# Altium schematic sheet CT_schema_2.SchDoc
size 276 x 169 mm
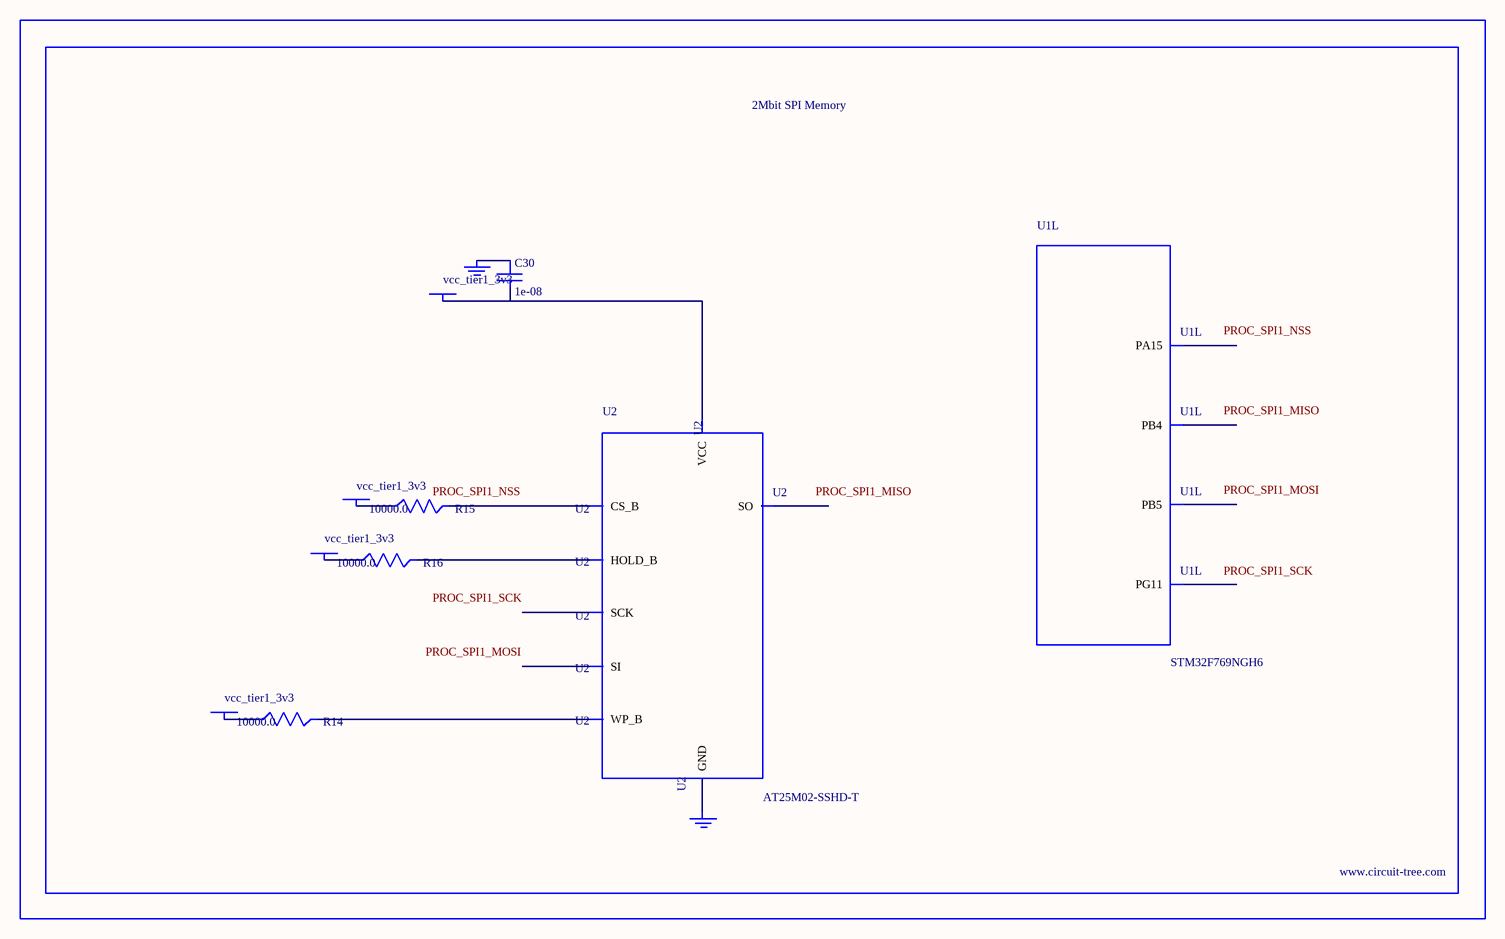
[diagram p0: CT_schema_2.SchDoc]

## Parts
BORDER1  (no value)
C30  1e-08  [C0402]
GND_INSTANCE_1_0  (no value)
GND_INSTANCE_1_1  (no value)
POWER_INSTANCE_1_0  vcc_tier1_3v3
POWER_INSTANCE_1_1  vcc_tier1_3v3
POWER_INSTANCE_1_2  vcc_tier1_3v3
POWER_INSTANCE_1_3  vcc_tier1_3v3
R14  10000.0  [R0603]
R15  10000.0  [R0603]
R16  10000.0  [R0603]
U1  STM32F769NGH6  [TFBGA216]  (part L of 17)
U2  AT25M02-SSHD-T  [SOIC-8]

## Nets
NetC30_1: C30.1 GND_INSTANCE_1_0.0(GND)
NetC30_2: C30.2 POWER_INSTANCE_1_3.0(PWR) U2.8(VCC)
NetGND_INSTANCE_1_1_0: GND_INSTANCE_1_1.0(GND) U2.4(GND)
NetPOWER_INSTANCE_1_0_0: POWER_INSTANCE_1_0.0(PWR) R15.1
NetPOWER_INSTANCE_1_1_0: POWER_INSTANCE_1_1.0(PWR) R14.1
NetPOWER_INSTANCE_1_2_0: POWER_INSTANCE_1_2.0(PWR) R16.1
NetR14_2: R14.2 U2.3(WP_B)
NetR15_2: R15.2 U2.1(CS_B)
NetR16_2: R16.2 U2.7(HOLD_B)

Not connected (* = marked no-connect by the designer): U1 A8(PB5) A9(PB4) A13(PA15) B8(PG11); U2 2(SO) 5(SI) 6(SCK)

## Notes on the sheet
- Labels drawn without touching a wire or pin: PROC_SPI1_MISO, PROC_SPI1_MOSI, PROC_SPI1_NSS, PROC_SPI1_SCK

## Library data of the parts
BORDER1 = BORDER_PAGE1
C30 = C0402C103K3RAC
GND_INSTANCE_1_0 GND_INSTANCE_1_1 = GND
POWER_INSTANCE_1_0-POWER_INSTANCE_1_3 = PWR
R14-R16 = RC0603JR-0710KL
